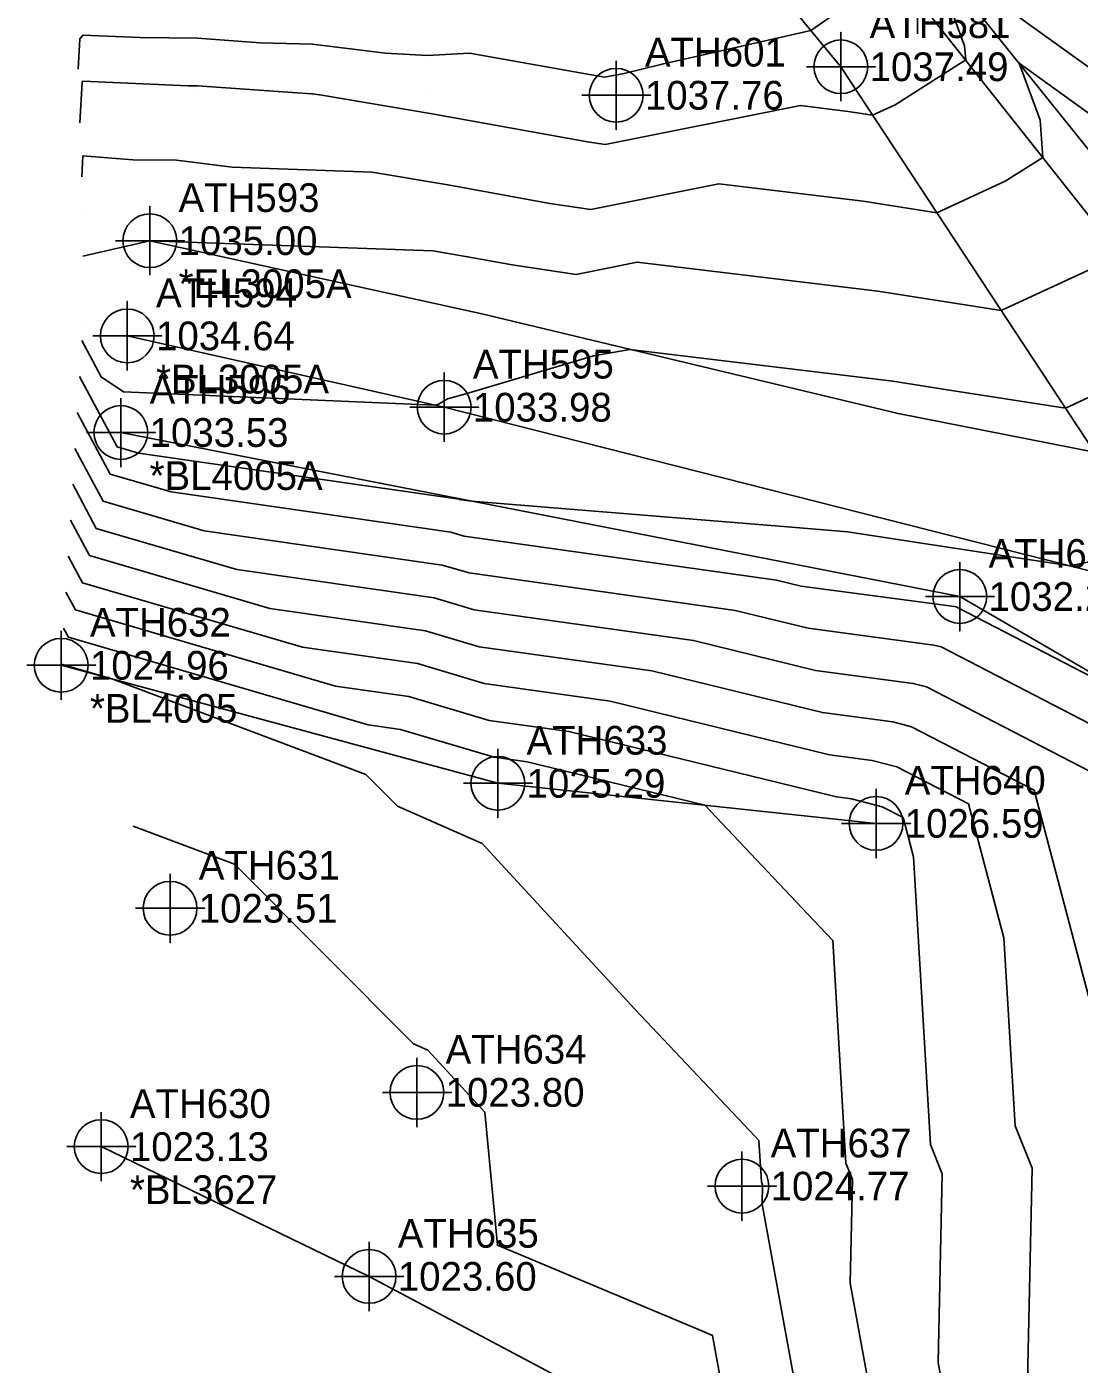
# Model space of a CAD drawing. Extents: x 1213164 to 1213550, y 766120 to 766870.
# Drawn here: x 1213225.1 to 1213316.7, y 766539.5 to 766656 of the extents above; entities that cross this region are included whole.
import ezdxf

# ---------------------------------------------------------------- set-up
doc = ezdxf.new("R2010")
doc.units = 0
for name, color, linetype in [('Default', 7, 'Continuous'), ('Exist DTM Breakline', 7, 'Continuous'), ('Exist DTM Breakline Cogo Comment', 7, 'Continuous'), ('Exist DTM Breakline Cogo Elevation', 7, 'Continuous'), ('Exist DTM Breakline Cogo Number', 7, 'Continuous'), ('Exist DTM Breakline Cogo Point CELL', 7, 'Continuous'), ('Exist DTM QL2 LIDAR Elevation Point', 7, 'Continuous'), ('Exist DTM Regular Point CELL', 7, 'Continuous'), ('Exist DTM Regular Point Cogo Elevation', 7, 'Continuous'), ('Exist DTM Regular Point Cogo Number', 7, 'Continuous'), ('Exist Environmental Wetland Boundary Cogo Comment', 7, 'Continuous'), ('Exist Environmental Wetland Boundary Cogo Elevation', 7, 'Continuous'), ('Exist Environmental Wetland Boundary Cogo Number', 7, 'Continuous'), ('Exist Environmental Wetland Boundary Cogo Point CELL', 7, 'Continuous'), ('Exist Hydro Stream or Body of Water', 7, 'Continuous'), ('Exist Roads Soil', 7, 'Continuous'), ('Exist Roads Soil Cogo Comment', 7, 'Continuous'), ('Exist Roads Soil Cogo Elevation', 7, 'Continuous'), ('Exist Roads Soil Cogo Number', 7, 'Continuous'), ('Exist Roads Soil Cogo Point CELL', 7, 'Continuous')]:
    doc.layers.add(name, color=color, linetype=linetype)

msp = doc.modelspace()

# ---------------------------------------------------------------- linework, layer by layer
at = {"layer": 'Default'}
for points in [[(1213229.91, 766628.63), (1213231.61, 766625.47), (1213233.56, 766624.18), (1213260.61, 766623.01), (1213260.95, 766623.11), (1213261.75, 766623.57), (1213263.33, 766624), (1213274.44, 766627.3), (1213277.6, 766627.87), (1213300.48, 766625.1), (1213305.42, 766624.33), (1213315.52, 766622.75), (1213319.13, 766624.42), (1213326.96, 766627.62), (1213327.29, 766630.38), (1213326.85, 766633.66), (1213334.04, 766628.84), (1213339.8, 766625.45), (1213343.74, 766626.32), (1213352.15, 766643.03), (1213353.46, 766646.12), (1213362.47, 766669.52)], [(1213230, 766635.98), (1213235.84, 766637.33), (1213260.48, 766636.44), (1213263.49, 766635.93), (1213267.36, 766635.23), (1213272.93, 766634.4), (1213278.24, 766635.46), (1213299.19, 766632.93), (1213309.93, 766631.26), (1213319.85, 766635.85), (1213320.25, 766636.1), (1213319.86, 766641.32), (1213319.16, 766643.22), (1213323.53, 766640.07), (1213326.46, 766638.34), (1213335.77, 766632.11), (1213340.35, 766629.41), (1213343.48, 766630.1), (1213350.16, 766643.38), (1213352.12, 766648.01), (1213359.49, 766667.16)], [(1213229.91, 766642.9), (1213230, 766644.71), (1213234.36, 766644.36), (1213238.15, 766644.35), (1213243, 766643.74), (1213255.18, 766643.3), (1213261.95, 766642.16), (1213270.65, 766640.58), (1213274.2, 766640.05), (1213285.35, 766642.28), (1213297.9, 766640.76), (1213304.33, 766639.76), (1213310.28, 766642.51), (1213313.54, 766644.58), (1213313.3, 766647.81), (1213311.48, 766652.77), (1213322.92, 766644.54), (1213330.59, 766639.99), (1213337.5, 766635.37), (1213340.89, 766633.37), (1213343.21, 766633.88), (1213348.17, 766643.73), (1213350.78, 766649.9), (1213356.51, 766664.8)], [(1213305.9, 766660.82), (1213322.31, 766649.01), (1213334.72, 766641.65), (1213339.22, 766638.63), (1213341.44, 766637.33), (1213342.95, 766637.66), (1213346.18, 766644.08), (1213349.44, 766651.8), (1213353.54, 766662.44)], [(1213229.75, 766647.58), (1213229.94, 766651.13), (1213230, 766651.21), (1213239.18, 766650.82), (1213240, 766650.81), (1213249.9, 766650.1), (1213250, 766650.1), (1213250.82, 766650), (1213260.4, 766648.38), (1213273.93, 766645.93), (1213275.46, 766645.7), (1213292.45, 766649.1), (1213296.61, 766648.59), (1213298.73, 766648.26), (1213300.7, 766649.17), (1213306.83, 766653.06), (1213306.74, 766654.3), (1213304.61, 766660.11)], [(1213229.6, 766652.25), (1213229.74, 766654.89), (1213230, 766655.22), (1213234.99, 766655.01), (1213240, 766654.95), (1213245.44, 766654.56), (1213250, 766654.43), (1213256.34, 766653.66), (1213260, 766653.45), (1213263.65, 766653.65), (1213275.41, 766651.57), (1213277.1, 766651.89), (1213280.41, 766652.7), (1213293.35, 766655.64), (1213297.85, 766658.75)], [(1213229.72, 766625.5), (1213233, 766619.37), (1213234.85, 766618.83), (1213262.75, 766614.82), (1213262.77, 766614.81), (1213263.84, 766614.66), (1213291.33, 766612.41), (1213296.54, 766611.98), (1213315.9, 766609.02), (1213317.84, 766609.42)], [(1213229.52, 766622.38), (1213232.39, 766617.01), (1213237.7, 766615.46), (1213262.02, 766611.96), (1213263.2, 766611.6), (1213290.37, 766607.78), (1213292.51, 766607.26), (1213305.85, 766605.48), (1213305.99, 766605.45), (1213323.05, 766596.62)], [(1213229.32, 766619.25), (1213231.79, 766614.64), (1213240.56, 766612.08), (1213261.29, 766609.09), (1213263.64, 766608.4), (1213286.76, 766605.14), (1213293.13, 766603.59), (1213304.06, 766602.13), (1213304.7, 766601.97), (1213324.2, 766591.88)], [(1213229.13, 766616.12), (1213231.18, 766612.28), (1213243.42, 766608.7), (1213260.57, 766606.23), (1213264.07, 766605.19), (1213283.14, 766602.51), (1213293.75, 766599.91), (1213302.27, 766598.78), (1213303.41, 766598.49), (1213318.49, 766590.68)], [(1213228.93, 766612.99), (1213230.58, 766609.91), (1213246.27, 766605.32), (1213259.84, 766603.37), (1213264.51, 766601.98), (1213279.53, 766599.87), (1213294.36, 766596.24), (1213300.48, 766595.43), (1213302.13, 766595.01), (1213312.79, 766589.49), (1213318.03, 766569.59)], [(1213228.73, 766609.86), (1213229.97, 766607.55), (1213249.13, 766601.94), (1213259.12, 766600.51), (1213264.94, 766598.77), (1213275.91, 766597.23), (1213294.98, 766592.57), (1213298.68, 766592.08), (1213300.84, 766591.53), (1213307.09, 766588.29), (1213310.16, 766576.64), (1213311.13, 766560.27), (1213312.61, 766556.57), (1213312.1, 766532.79)], [(1213228.53, 766606.74), (1213229.37, 766605.18), (1213251.99, 766598.56), (1213258.39, 766597.64), (1213265.38, 766595.57), (1213272.3, 766594.59), (1213295.6, 766588.9), (1213296.89, 766588.73), (1213299.56, 766588.04), (1213301.39, 766587.1), (1213302.28, 766583.69), (1213303.77, 766558.65), (1213304.79, 766556.09), (1213304.44, 766539.67), (1213306.32, 766529.41)], [(1213228.34, 766603.61), (1213228.76, 766602.81), (1213254.84, 766595.19), (1213257.66, 766594.78), (1213265.81, 766592.36), (1213268.68, 766591.95), (1213284.12, 766588.18), (1213293.58, 766578.18), (1213295.26, 766576.41), (1213296.41, 766557.02), (1213296.97, 766555.61), (1213296.78, 766546.56), (1213299.77, 766530.21)], [(1213228.14, 766600.48), (1213228.16, 766600.45), (1213232.61, 766599.15), (1213254.65, 766590.86), (1213257.39, 766588.11), (1213264.75, 766584.84), (1213278.03, 766570.43), (1213288.52, 766559.33), (1213288.84, 766559), (1213289.05, 766555.39), (1213289.16, 766555.13), (1213289.12, 766553.44), (1213293.22, 766531.01)], [(1213234.39, 766586.37), (1213243.22, 766583.05), (1213258.79, 766567.41), (1213260.04, 766566.85), (1213265, 766561.47), (1213266.09, 766549.87), (1213283.94, 766542.4), (1213284.8, 766542.03), (1213286.67, 766531.82)]]:
    msp.add_lwpolyline(points, dxfattribs=at)
at = {"layer": 'Exist DTM Breakline'}
for points in [[(1213258.22, 766718.72), (1213280.97, 766690.21), (1213305.18, 766660.62), (1213332.72, 766626.34), (1213338.93, 766619.05), (1213344.38, 766617.29)], [(1213233.32, 766620.63), (1213306.32, 766606.35), (1213329.35, 766592.96), (1213324.12, 766557.27), (1213317.07, 766526.75)], [(1213228.13, 766600.36), (1213266.12, 766590.09), (1213299.03, 766586.6)]]:
    msp.add_lwpolyline(points, dxfattribs=at)
at = {"layer": 'Exist DTM Breakline Cogo Point CELL'}
for points in [[(1213233.32, 766623.63), (1213233.32, 766617.63), (1213233.32, 766620.63), (1213236.32, 766620.63), (1213230.32, 766620.63)], [(1213306.32, 766609.35), (1213306.32, 766603.35), (1213306.32, 766606.35), (1213309.32, 766606.35), (1213303.32, 766606.35)], [(1213228.13, 766603.36), (1213228.13, 766597.36), (1213228.13, 766600.36), (1213231.13, 766600.36), (1213225.13, 766600.36)], [(1213266.12, 766593.09), (1213266.12, 766587.09), (1213266.12, 766590.09), (1213269.12, 766590.09), (1213263.12, 766590.09)], [(1213299.03, 766589.6), (1213299.03, 766583.6), (1213299.03, 766586.6), (1213302.03, 766586.6), (1213296.03, 766586.6)]]:
    msp.add_lwpolyline(points, dxfattribs=at)
for centre in [(1213233.32, 766620.63), (1213306.32, 766606.35), (1213228.13, 766600.36), (1213266.12, 766590.09), (1213299.03, 766586.6)]:
    msp.add_circle(centre, 2.34, dxfattribs=at)
at = {"layer": 'Exist DTM QL2 LIDAR Elevation Point'}
for p, q in [((1213230, 766650), (1213230, 766650)), ((1213240, 766650), (1213240, 766650)), ((1213250, 766650), (1213250, 766650)), ((1213260, 766650), (1213260, 766650)), ((1213230, 766640), (1213230, 766640)), ((1213230, 766630), (1213230, 766630))]:
    msp.add_line(p, q, dxfattribs=at)
at = {"layer": 'Exist DTM Regular Point CELL'}
for points in [[(1213276.42, 766652.99), (1213276.42, 766646.99), (1213276.42, 766649.99), (1213279.42, 766649.99), (1213273.42, 766649.99)], [(1213237.6, 766582.21), (1213237.6, 766576.21), (1213237.6, 766579.21), (1213240.6, 766579.21), (1213234.6, 766579.21)], [(1213259.08, 766566.18), (1213259.08, 766560.18), (1213259.08, 766563.18), (1213262.08, 766563.18), (1213256.08, 766563.18)], [(1213287.36, 766558.02), (1213287.36, 766552.02), (1213287.36, 766555.02), (1213290.36, 766555.02), (1213284.36, 766555.02)]]:
    msp.add_lwpolyline(points, dxfattribs=at)
for centre in [(1213276.42, 766649.99), (1213237.6, 766579.21), (1213259.08, 766563.18), (1213287.36, 766555.02)]:
    msp.add_circle(centre, 2.34, dxfattribs=at)
at = {"layer": 'Exist Environmental Wetland Boundary Cogo Point CELL'}
for points in [[(1213231.61, 766561.46), (1213231.61, 766555.46), (1213231.61, 766558.46), (1213234.61, 766558.46), (1213228.61, 766558.46)], [(1213254.92, 766550.16), (1213254.92, 766544.16), (1213254.92, 766547.16), (1213257.92, 766547.16), (1213251.92, 766547.16)]]:
    msp.add_lwpolyline(points, dxfattribs=at)
for centre in [(1213231.61, 766558.46), (1213254.92, 766547.16)]:
    msp.add_circle(centre, 2.34, dxfattribs=at)
at = {"layer": 'Exist Hydro Stream or Body of Water'}
msp.add_lwpolyline([(1213231.61, 766558.46), (1213254.92, 766547.16), (1213282.88, 766532.28), (1213282.71, 766524.45), (1213298.43, 766515.16), (1213316.53, 766508.53)], dxfattribs=at)
at = {"layer": 'Exist Roads Soil'}
for points in [[(1213255.38, 766715.7), (1213279.2, 766688.85), (1213302.65, 766658.35), (1213330, 766623.78), (1213351.29, 766609.62)], [(1213247.96, 766710.32), (1213271.31, 766682.36), (1213295.97, 766652.47)], [(1213295.97, 766652.47), (1213318.05, 766618.91), (1213300.95, 766622.28), (1213264.73, 766630.95), (1213235.84, 766637.33)], [(1213233.88, 766629.04), (1213261.45, 766622.83), (1213319.9, 766608), (1213346.63, 766593.15)]]:
    msp.add_lwpolyline(points, dxfattribs=at)
at = {"layer": 'Exist Roads Soil Cogo Point CELL'}
for points in [[(1213302.65, 766655.35), (1213302.65, 766661.35), (1213302.65, 766658.35), (1213305.65, 766658.35), (1213299.65, 766658.35)], [(1213295.97, 766649.47), (1213295.97, 766655.47), (1213295.97, 766652.47), (1213298.97, 766652.47), (1213292.97, 766652.47)], [(1213235.84, 766634.33), (1213235.84, 766640.33), (1213235.84, 766637.33), (1213238.84, 766637.33), (1213232.84, 766637.33)], [(1213233.88, 766626.04), (1213233.88, 766632.04), (1213233.88, 766629.04), (1213236.88, 766629.04), (1213230.88, 766629.04)], [(1213261.45, 766619.83), (1213261.45, 766625.83), (1213261.45, 766622.83), (1213264.45, 766622.83), (1213258.45, 766622.83)]]:
    msp.add_lwpolyline(points, dxfattribs=at)
for centre in [(1213295.97, 766652.47), (1213235.84, 766637.33), (1213233.88, 766629.04), (1213261.45, 766622.83)]:
    msp.add_circle(centre, 2.34, dxfattribs=at)

# ---------------------------------------------------------------- texts
at = {"layer": 'Exist DTM Breakline Cogo Comment'}
for s, p in [('*BL4005A', (1213235.82, 766615.63)), ('*BL4005', (1213230.63, 766595.36))]:
    msp.add_text(s, height=2.5, dxfattribs=at).set_placement(p)
at = {"layer": 'Exist DTM Breakline Cogo Elevation'}
for s, p in [('1033.53', (1213235.82, 766619.38)), ('1032.26', (1213308.82, 766605.1)), ('1024.96', (1213230.63, 766599.11)), ('1025.29', (1213268.62, 766588.84)), ('1026.59', (1213301.53, 766585.35))]:
    msp.add_text(s, height=2.5, dxfattribs=at).set_placement(p)
at = {"layer": 'Exist DTM Breakline Cogo Number'}
for s, p in [('ATH596', (1213235.82, 766623.13)), ('ATH603', (1213308.82, 766608.85)), ('ATH632', (1213230.63, 766602.86)), ('ATH633', (1213268.62, 766592.59)), ('ATH640', (1213301.53, 766589.1))]:
    msp.add_text(s, height=2.5, dxfattribs=at).set_placement(p)
at = {"layer": 'Exist DTM Regular Point Cogo Elevation'}
for s, p in [('1037.76', (1213278.92, 766648.74)), ('1023.51', (1213240.1, 766577.96)), ('1023.80', (1213261.58, 766561.93)), ('1024.77', (1213289.86, 766553.77))]:
    msp.add_text(s, height=2.5, dxfattribs=at).set_placement(p)
at = {"layer": 'Exist DTM Regular Point Cogo Number'}
for s, p in [('ATH601', (1213278.92, 766652.49)), ('ATH631', (1213240.1, 766581.71)), ('ATH634', (1213261.58, 766565.68)), ('ATH637', (1213289.86, 766557.52))]:
    msp.add_text(s, height=2.5, dxfattribs=at).set_placement(p)
at = {"layer": 'Exist Environmental Wetland Boundary Cogo Comment'}
msp.add_text('*BL3627', height=2.5, dxfattribs=at).set_placement((1213234.11, 766553.46))
at = {"layer": 'Exist Environmental Wetland Boundary Cogo Elevation'}
for s, p in [('1023.13', (1213234.11, 766557.21)), ('1023.60', (1213257.42, 766545.91))]:
    msp.add_text(s, height=2.5, dxfattribs=at).set_placement(p)
at = {"layer": 'Exist Environmental Wetland Boundary Cogo Number'}
for s, p in [('ATH630', (1213234.11, 766560.96)), ('ATH635', (1213257.42, 766549.66))]:
    msp.add_text(s, height=2.5, dxfattribs=at).set_placement(p)
at = {"layer": 'Exist Roads Soil Cogo Comment'}
for s, p in [('*EL3005A', (1213238.34, 766632.33)), ('*BL3005A', (1213236.38, 766624.04))]:
    msp.add_text(s, height=2.5, dxfattribs=at).set_placement(p)
at = {"layer": 'Exist Roads Soil Cogo Elevation'}
for s, p in [('1037.49', (1213298.47, 766651.22)), ('1035.00', (1213238.34, 766636.08)), ('1034.64', (1213236.38, 766627.79)), ('1033.98', (1213263.95, 766621.58))]:
    msp.add_text(s, height=2.5, dxfattribs=at).set_placement(p)
at = {"layer": 'Exist Roads Soil Cogo Number'}
for s, p in [('ATH581', (1213298.47, 766654.97)), ('ATH593', (1213238.34, 766639.83)), ('ATH594', (1213236.38, 766631.54)), ('ATH595', (1213263.95, 766625.33))]:
    msp.add_text(s, height=2.5, dxfattribs=at).set_placement(p)

doc.saveas('drawing.dxf')
